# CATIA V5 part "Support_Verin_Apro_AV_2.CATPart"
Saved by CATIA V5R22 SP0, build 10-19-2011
Part number: Support_Verin_Apro_AV_2
Bounding box of the stored display mesh (mm): x 0 to 9, y -25 to 25, z -12 to 15
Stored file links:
  U:\S9A\PER\CAO\Assemblage\Reservoir_Boite\Verin\Test_Poussoir_2\Test\Support_Verin_Apro_AV_2.CATPart
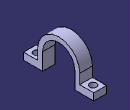
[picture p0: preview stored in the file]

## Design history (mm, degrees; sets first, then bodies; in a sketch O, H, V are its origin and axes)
Body1 (main body)
  Sketch1 on yz-plane, origin (0, 0, 0), H (0, 1, 0), V (0, 0, 1)
    arc A1 centre (0, 0) radius 11.5 from (11.5, 0) to (-11.5, 0) ccw
    point P1 (-11.5, 0)
    line L1 (-15, 0) -> (-15, -7)
    line L2 (-15, -12) -> (-11.5, -12)
    line L3 (-11.5, -12) -> (-11.5, 0)
    point P2 (-15, 0)
    point P3 (-15, -12)
    point P4 (-11.5, -12)
    axis line L4 (-25, -12) -> (25, -12)
    point P5 (-25, -12)
    point P6 (25, -12)
    line L5 (-15, -12) -> (-25, -12)
    line L6 (-25, -12) -> (-25, -7)
    line L7 (-25, -7) -> (-15, -7)
    point P7 (-25, -12)
    point P8 (-25, -7)
    point P9 (-15, -7)
    point P10 (15, -12)
    point P11 (11.5, -12)
    point P12 (25, -12)
    point P13 (25, -7)
    point P14 (15, -7)
    line L8 (15, -12) -> (11.5, -12)
    line L9 (15, -12) -> (25, -12)
    line L10 (25, -12) -> (25, -7)
    line L11 (25, -7) -> (15, -7)
    point P15 (11.5, 0)
    line L12 (11.5, -12) -> (11.5, 0)
    point P16 (15, 0)
    line L13 (15, 0) -> (15, -7)
    arc A2 centre (0, 0) radius 15 from (15, 0) to (-15, 0) ccw
    radius A1 = 11.5
    length L6 = 5
    length L7 = 10
    distance A1 A2 = 3.5
    distance L13 L12 = 3.5
    distance L4 A1 = 0.5
    horizontal: L2 H, L4 H, L5 H, L7 H
    vertical: L1 V, L3 V, L6 V
    tangency: A1 L3
    coincidence: L2 L4, P3 L1, P5 P7, P6 P12
    symmetry: P3 P10 V, P4 P11 V, P7 P12 V, P8 P13 V, P9 P14 V, L2 L8 V, L5 L9 V, L6 L10 V, L7 L11 V, P1 P15 V, L3 L12 V, P2 P16 V, L1 L13 V
  Pad1: profile Sketch1, direction (1, 0, 0), length 9
  Sketch2 on face of Pad1 from Sketch1.L7, origin (3.9526, -22.6085, -7), H (1, 0, 0), V (0, 1, 0)
    point P1 (0.5474, 2.6085)
    reference projected point E3 (-3.9526, 7.6085) from vertex [face of Pad1 from Sketch1.L1 | start face of Pad1 | face of Pad1 from Sketch1.A2]
    reference projected point E4 (5.0474, -2.3915) from vertex [face of Pad1 from Sketch1.L6 | end face of Pad1 | face of Pad1 from Sketch1.L7]
    reference projected point E5 (-3.9526, -2.3915) from vertex [face of Pad1 from Sketch1.L6 | start face of Pad1 | face of Pad1 from Sketch1.L7]
    reference projected point E6 (5.0474, 7.6085) from vertex [face of Pad1 from Sketch1.L1 | end face of Pad1 | face of Pad1 from Sketch1.A2]
    equidistance: E3 E4 P1, E5 E6 P1
  Hole1: placed by Sketch2, at (4.5, -20, -7) direction (0, 0, -1), diameter 5, through (limit type 6)
  Mirror1: of Hole1, about zx-plane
